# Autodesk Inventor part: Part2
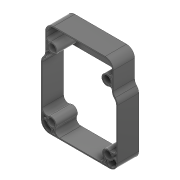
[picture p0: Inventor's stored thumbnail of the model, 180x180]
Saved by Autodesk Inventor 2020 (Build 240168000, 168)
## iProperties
Created: 2020-11
Part Number: Part2
Material: ABS Plastic
Document SubType Name: Modeling
Designer: Greg
Density: 1.06 g/cm^3
Appearance: Smooth - Black
Author: Greg
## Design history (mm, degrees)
sketch "Sketch1"
  geometry: L1 (0, 0)-(101.6, 0); L2 (101.6, 0)-(101.6, 82.55); L3 (101.6, 82.55)-(95.885, 82.55); L4 (95.885, 82.55)-(95.885, 127); L5 (95.885, 127)-(5.715, 127); L6 (5.715, 127)-(5.715, 82.55); L7 (5.715, 82.55)-(0, 82.55); L8 (0, 82.55)-(0, 0); L9 (4.115, 128.6)-(97.485, 128.6); L10 (97.485, 128.6)-(97.485, 84.15); L11 (97.485, 84.15)-(103.2, 84.15); L12 (103.2, 84.15)-(103.2, -1.6); L13 (103.2, -1.6)-(-1.6, -1.6); L14 (-1.6, -1.6)-(-1.6, 84.15); L15 (-1.6, 84.15)-(4.115, 84.15); L16 (4.115, 84.15)-(4.115, 128.6); L17 (13.208, 101.6)-(88.392, 101.6); L18 (12.154, 12.7)-(89.446, 12.7); C1 r 5.271 at (13.208, 101.6); C2 r 6.871 at (13.208, 101.6); C3 r 5.271 at (88.392, 101.6); C4 r 6.871 at (88.392, 101.6); C5 r 6.871 at (89.446, 12.7); C6 r 5.271 at (89.446, 12.7); C7 r 5.271 at (12.154, 12.7); C8 r 6.871 at (12.154, 12.7); 4 further points
  constraints: 36 end point, 11 perpendicular, 8 centre point, 4 coincident, 4 midpoint, 3 horizontal, 2 horizontal alignment, 2 point on line, 2 vertical alignment, 1 collinear, 1 vertical
  dimensions: "d0" = 101.6 distance of L1.start L1.end; "d1" = 127 distance between parallel lines of L5 L1; "d2" = 44.45 distance between parallel lines of L5 L7; "d3" = 5.715 distance between parallel lines of L6 L8; "d4" = 5.715 distance between parallel lines of L2 L4 (derived); "d10" = 1.6002 distance between parallel lines of L5 L9; "d11" = 1.6002 distance between parallel lines of L6 L16 (= d10); "d12" = 1.6002 distance between parallel lines of L7 L15 (= d10); "d13" = 1.6002 distance between parallel lines of L8 L14 (= d10); "d15" = 1.6002 distance between parallel lines of L1 L13 (= d10); "d16" = 1.6002 distance between parallel lines of L4 L10 (= d10); "d17" = 1.6002 distance between parallel lines of L3 L11 (= d10); "d18" = 1.6002 distance between parallel lines of L12 L2 (= d10); "d31" = 13.741 diameter of C2 (= d32 + 2 x d42); "d32" = 10.541 diameter of C1; "d33" = 13.741 diameter of C4 (= d31); "d34" = 13.741 diameter of C5 (= d31); "d35" = 13.741 diameter of C8 (= d31); "d36" = 10.541 diameter of C3 (= d32); "d37" = 10.541 diameter of C6 (= d32); "d38" = 10.541 diameter of C7 (= d32); "d39" = 77.2922 distance of L18.start L18.end; "d41" = 75.184 distance of L17.start L17.end; "d44" = 12.7 distance from line of L1 C5.centre; "d45" = 88.9 vertical distance of L18.end L17.end
extrude "Extrusion1" new body sketch "Sketch1" distance "d20" = 29.21; taper "d21" = 0 deg
fillet "Fillet1" dims "d22" = 9.525
fillet "Fillet2" dims "d23" = 11.1252 (computed from d10)
fillet "Fillet3" dims "d48" = 7.9248 (computed from d10)
sketch "Sketch2"
  geometry: L1 (92.075, 0)-(9.525, 0) reference; L2 (0, 9.525)-(0, 82.55) reference; L3 (50.8, 0)-(50.8, 28.668); L4 (9.525, 0)-(92.075, 0); L5 (101.6, 9.525)-(101.6, 82.55); L6 (101.6, 9.525)-(101.6, 82.55); C1 r 5.271 at (12.154, 12.7) reference; C2 r 5.271 at (89.446, 12.7); A1 r 9.525 centre (9.525, 9.525) between (0, 9.525) and (9.525, 0) reference; A2 r 3.2 centre (8.81, 3.2) between (8.81, 0) and (9.873, 6.219); A3 r 4.801 centre (8.81, 3.2) between (12.388, 0) and (12.806, 5.861); A4 r 3.2 centre (3.2, 8.089) between (6.046, 9.555) and (0, 8.089); A5 r 4.801 centre (3.2, 8.089) between (5.289, 12.412) and (0, 11.668); A6 r 6.35 centre (23.75, 6.35) between (18.18, 9.4) and (23.75, 0); A7 r 7.95 centre (23.75, 6.35) between (15.818, 6.888) and (18.966, 0); A8 r 7.95 centre (6.35, 24.578) between (0, 19.795) and (6.518, 16.63); A9 r 6.35 centre (6.35, 24.578) between (0, 24.578) and (9.138, 18.873); A10 r 6.871 centre (12.154, 12.7) between (15.818, 6.888) and (18.18, 9.4) reference; A11 r 6.871 centre (12.154, 12.7) between (9.138, 18.873) and (6.518, 16.63) reference; A12 r 7.95 centre (95.25, 24.578) between (95.082, 16.63) and (101.6, 19.795); A13 r 6.35 centre (95.25, 24.578) between (92.462, 18.873) and (101.6, 24.578); A14 r 4.801 centre (98.4, 8.089) between (101.6, 11.668) and (96.311, 12.412); A15 r 3.2 centre (98.4, 8.089) between (101.6, 8.089) and (95.554, 9.555); A16 r 6.871 centre (89.446, 12.7) between (85.782, 6.888) and (83.42, 9.4); A17 r 6.871 centre (89.446, 12.7) between (92.462, 18.873) and (95.082, 16.63); A18 r 9.525 centre (92.075, 9.525) between (92.075, 0) and (101.6, 9.525); A19 r 3.2 centre (92.79, 3.2) between (91.727, 6.219) and (92.79, 0); A20 r 4.801 centre (92.79, 3.2) between (88.794, 5.861) and (89.212, 0); A21 r 7.95 centre (77.85, 6.35) between (82.634, 0) and (85.782, 6.888); A22 r 6.35 centre (77.85, 6.35) between (77.85, 0) and (83.42, 9.4); 26 further points
  constraints: 50 point on circle, 35 symmetric about line, 20 centre point, 12 point on line, 8 coincident, 8 end point, 8 tangent, 4 equal radius, 1 midpoint, 1 vertical, 12 other
  dimensions: "d24" = 3.2004 radius of A2; "d27" = 6.35 radius of A6; "d28" = 1.6002 radial gap between concentric circles of A6 A7 (= d10); "d29" = 1.6002 radial gap between concentric circles of A3 A2 (= d10)
extrude "Extrusion2" join sketch "Sketch2" distance "d46" = 29.21; taper "d47" = 0 deg
sketch "Sketch3"
  geometry: L1 (-7.493, -9.329)-(-7.493, 15.875) reference; L2 (37.592, 27.126)-(37.592, 0); L3 (82.677, -9.329)-(82.677, 15.875); A1 r 6.871 centre (0, 0) between (-2.369, 6.449) and (-5.282, -4.393) reference; A2 r 3.81 centre (-3.683, 10.025) between (-7.493, 10.025) and (-2.369, 6.449); A3 r 5.41 centre (-3.683, 10.025) between (-7.493, 6.184) and (-4.949, 4.765); A4 r 4.775 centre (-4.318, -9.07) between (-5.282, -4.393) and (-7.493, -5.503); A5 r 3.175 centre (-4.318, -9.07) between (-2.953, -6.203) and (-7.493, -9.07); A6 r 6.871 centre (0, 0) between (-2.369, 6.449) and (-5.282, -4.393) reference; A7 r 11.125 centre (-18.618, -9.329) between (-10.831, -17.274) and (-7.493, -9.329) reference; A8 r 6.871 centre (75.184, 0) between (77.553, 6.449) and (80.466, -4.393); A9 r 6.871 centre (75.184, 0) between (77.553, 6.449) and (80.466, -4.393); A10 r 5.41 centre (78.867, 10.025) between (80.133, 4.765) and (82.677, 6.184); A11 r 4.775 centre (79.502, -9.07) between (82.677, -5.503) and (80.466, -4.393); A12 r 3.175 centre (79.502, -9.07) between (82.677, -9.07) and (78.137, -6.203); A13 r 11.125 centre (93.802, -9.329) between (82.677, -9.329) and (86.015, -17.274); A14 r 3.81 centre (78.867, 10.025) between (77.553, 6.449) and (82.677, 10.025); 7 further points
  constraints: 28 point on circle, 19 symmetric about line, 11 centre point, 6 point on line, 4 coincident, 4 end point, 4 tangent, 1 vertical, 7 other
  dimensions: "d49" = 3.81 radius of A2; "d50" = 1.6002 radial gap between concentric circles of A3 A2 (= d10); "d51" = 3.175 radius of A5; "d52" = 1.6002 radial gap between concentric circles of A5 A4 (= d10)
extrude "Extrusion3" join sketch "Sketch3" distance "d53" = 29.21; taper "d54" = 0 deg
sketch "Sketch4"
  geometry: L1 (-95.885, 92.53)-(-5.715, 92.53); L2 (-5.715, 92.271)-(-5.715, 92.53) reference; L3 (0, 24.578)-(0, 78.667) reference; L4 (-77.85, 0)-(-23.75, 0) reference; L5 (-101.6, 78.667)-(-101.6, 24.578) reference; L6 (-95.885, 92.53)-(-95.885, 92.271) reference; L7 (-95.885, 117.475)-(-95.885, 111.625) reference; L8 (-15.24, 127)-(-86.36, 127) reference; L9 (-5.715, 111.625)-(-5.715, 117.475) reference; L10 (-95.885, 107.784)-(-95.885, 96.097) reference; L11 (-89.212, 0)-(-82.634, 0) reference; L12 (-9.525, -1.6)-(-92.075, -1.6) reference; L13 (1.6, 78.619)-(1.6, 9.525) reference; L14 (-4.115, 117.475)-(-4.115, 92.88) reference; L15 (-86.36, 128.6)-(-15.24, 128.6) reference; L16 (-97.485, 92.88)-(-97.485, 117.475) reference; L17 (-103.2, 9.525)-(-103.2, 78.619) reference; L18 (-18.966, 0)-(-12.388, 0) reference; L19 (0, 11.668)-(0, 19.795) reference; L20 (-101.6, 19.795)-(-101.6, 11.668) reference; L21 (-5.715, 96.097)-(-5.715, 107.784) reference; L22 (-95.885, 92.53)-(-97.492, 92.53); L23 (-5.715, 92.53)-(-4.108, 92.53); C1 r 5.271 at (-88.392, 101.6) reference; C2 r 5.271 at (-12.154, 12.7) reference; C3 r 5.271 at (-89.446, 12.7) reference; C4 r 5.271 at (-13.208, 101.6) reference; A1 r 3.175 centre (-92.71, 92.53) between (-91.345, 95.397) and (-95.885, 92.53) reference; A2 r 3.175 centre (-8.89, 92.53) between (-5.715, 92.53) and (-10.255, 95.397) reference; A3 r 6.871 centre (-13.208, 101.6) between (-10.839, 108.049) and (-10.255, 95.397) reference; A4 r 3.175 centre (-8.89, 92.53) between (-5.715, 92.53) and (-10.255, 95.397) reference; A5 r 11.125 centre (5.41, 92.271) between (-5.715, 92.271) and (-2.377, 84.326) reference; A6 r 7.925 centre (-7.925, 78.667) between (0, 78.667) and (-2.377, 84.326) reference; A7 r 6.35 centre (-6.35, 24.578) between (-9.138, 18.873) and (0, 24.578) reference; A8 r 6.871 centre (-12.154, 12.7) between (-9.138, 18.873) and (-18.18, 9.4) reference; A9 r 6.35 centre (-23.75, 6.35) between (-23.75, 0) and (-18.18, 9.4) reference; A10 r 6.35 centre (-77.85, 6.35) between (-83.42, 9.4) and (-77.85, 0) reference; A11 r 6.871 centre (-89.446, 12.7) between (-83.42, 9.4) and (-92.462, 18.873) reference; A12 r 6.35 centre (-95.25, 24.578) between (-101.6, 24.578) and (-92.462, 18.873) reference; A13 r 7.925 centre (-93.675, 78.667) between (-99.223, 84.326) and (-101.6, 78.667) reference; A14 r 11.125 centre (-107.01, 92.271) between (-99.223, 84.326) and (-95.885, 92.271) reference; A15 r 3.175 centre (-92.71, 92.53) between (-91.345, 95.397) and (-95.885, 92.53) reference; A16 r 6.871 centre (-88.392, 101.6) between (-91.345, 95.397) and (-90.761, 108.049) reference; A17 r 3.81 centre (-92.075, 111.625) between (-95.885, 111.625) and (-90.761, 108.049) reference; A18 r 9.525 centre (-86.36, 117.475) between (-86.36, 127) and (-95.885, 117.475) reference; A19 r 9.525 centre (-15.24, 117.475) between (-5.715, 117.475) and (-15.24, 127) reference; A20 r 3.81 centre (-9.525, 111.625) between (-10.839, 108.049) and (-5.715, 111.625) reference; A21 r 4.775 centre (-92.71, 92.53) between (-93.674, 97.207) and (-95.885, 96.097) reference; A22 r 5.41 centre (-92.075, 111.625) between (-95.885, 107.784) and (-93.341, 106.365) reference; A23 r 6.871 centre (-88.392, 101.6) between (-93.341, 106.365) and (-93.674, 97.207) reference; A24 r 6.871 centre (-89.446, 12.7) between (-88.794, 5.861) and (-85.782, 6.888) reference; A25 r 7.95 centre (-77.85, 6.35) between (-85.782, 6.888) and (-82.634, 0) reference; A26 r 4.801 centre (-92.79, 3.2) between (-89.212, 0) and (-88.794, 5.861) reference; A27 r 3.2 centre (-92.79, 3.2) between (-92.528, 0.011) and (-91.727, 6.219) reference; A28 r 9.525 centre (-92.075, 9.525) between (-101.556, 8.615) and (-92.528, 0.011) reference; A29 r 3.2 centre (-98.4, 8.089) between (-95.554, 9.555) and (-101.556, 8.615) reference; A30 r 6.871 centre (-89.446, 12.7) between (-95.554, 9.555) and (-91.727, 6.219) reference; A31 r 11.125 centre (-92.075, 9.525) between (-103.2, 9.525) and (-92.075, -1.6) reference; A32 r 11.125 centre (-9.525, 9.525) between (-9.525, -1.6) and (1.6, 9.525) reference; A33 r 11.125 centre (-9.525, 78.619) between (1.6, 78.619) and (-1.479, 86.302) reference; A34 r 9.525 centre (5.41, 92.88) between (-4.115, 92.88) and (-1.479, 86.302) reference; A35 r 11.125 centre (-15.24, 117.475) between (-4.115, 117.475) and (-15.24, 128.6) reference; A36 r 11.125 centre (-86.36, 117.475) between (-86.36, 128.6) and (-97.485, 117.475) reference; A37 r 9.525 centre (-107.01, 92.88) between (-100.121, 86.302) and (-97.485, 92.88) reference; A38 r 11.125 centre (-92.075, 78.619) between (-100.121, 86.302) and (-103.2, 78.619) reference; A39 r 4.801 centre (-8.81, 3.2) between (-12.806, 5.861) and (-12.388, 0) reference; A40 r 7.95 centre (-23.75, 6.35) between (-18.966, 0) and (-15.818, 6.888) reference; A41 r 6.871 centre (-12.154, 12.7) between (-15.818, 6.888) and (-12.806, 5.861) reference; A42 r 6.871 centre (-12.154, 12.7) between (-5.289, 12.412) and (-6.518, 16.63) reference; A43 r 7.95 centre (-6.35, 24.578) between (-6.518, 16.63) and (0, 19.795) reference; A44 r 4.801 centre (-3.2, 8.089) between (0, 11.668) and (-5.289, 12.412) reference; A45 r 6.871 centre (-12.154, 12.7) between (-9.873, 6.219) and (-6.046, 9.555) reference; A46 r 3.2 centre (-3.2, 8.089) between (-0.044, 8.615) and (-6.046, 9.555) reference; A47 r 9.525 centre (-9.525, 9.525) between (-9.072, 0.011) and (-0.044, 8.615) reference; A48 r 3.2 centre (-8.81, 3.2) between (-9.873, 6.219) and (-9.072, 0.011) reference; A49 r 4.801 centre (-98.4, 8.089) between (-96.311, 12.412) and (-101.6, 11.668) reference; A50 r 7.95 centre (-95.25, 24.578) between (-101.6, 19.795) and (-95.082, 16.63) reference; A51 r 6.871 centre (-89.446, 12.7) between (-95.082, 16.63) and (-96.311, 12.412) reference; A52 r 5.41 centre (-9.525, 111.625) between (-8.259, 106.365) and (-5.715, 107.784) reference; A53 r 4.775 centre (-8.89, 92.53) between (-5.715, 96.097) and (-7.926, 97.207) reference; A54 r 6.871 centre (-13.208, 101.6) between (-7.926, 97.207) and (-8.259, 106.365) reference; A55 r 9.525 centre (-107.01, 92.88) between (-100.121, 86.302) and (-97.485, 92.88) reference; 4 further points
  constraints: 6 end point, 3 point on circle, 1 horizontal, 1 point on line
extrude "Extrusion4" join sketch "Sketch4" distance "d55" = 1.27; taper "d56" = 0 deg
sketch "Sketch5"
  geometry: 1 further point
sketch "Sketch6"
  geometry: L1 (15.24, 127)-(86.36, 127) reference; C1 r 4.508 at (50.8, 112.42); 2 further points
  constraints: 1 centre point, 1 midpoint, 1 vertical alignment
  dimensions: "d57" = 14.5796 distance from line of L1 C1.centre; "d58" = 9.017 diameter of C1
extrude "Extrusion5" cut sketch "Sketch6" distance "d59" = 1.27; taper "d60" = 0 deg
body "Solid1"
node "Projected Loop1"
node "Projected Loop2"
other parameters: "d42" = 1.6
